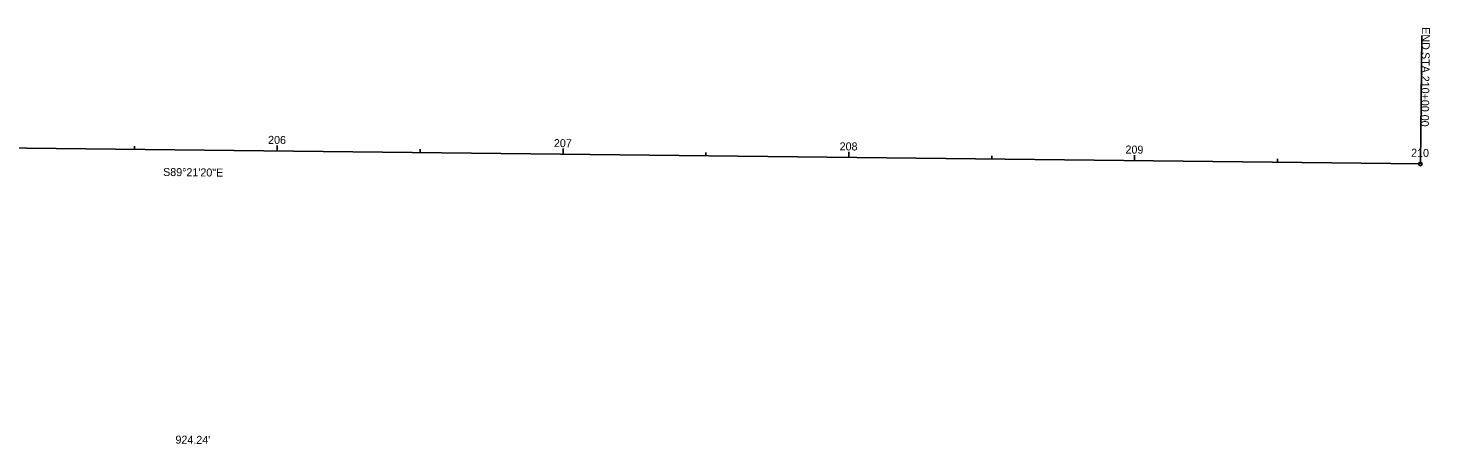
# Model space of a CAD drawing. Extents: x 1501024 to 1508874, y 327839 to 328839.
# Drawn here: x 1508383 to 1508873.6, y 328154.4 to 328299.9 of the extents above; entities that cross this region are included whole.
import ezdxf

# ---------------------------------------------------------------- set-up
doc = ezdxf.new("R2010")
doc.units = 0
for name, color, linetype in [('GE_X_Alignment', 7, 'Continuous'), ('GE_X_Alignment_100_Bearings', 7, 'Continuous'), ('GE_X_Alignment_100_Cardinal_Points', 7, 'Continuous'), ('GE_X_Alignment_100_Distances', 7, 'Continuous'), ('GE_X_Alignment_100_Stations', 7, 'Continuous'), ('GE_X_Alignment_500_Bearings', 7, 'Continuous'), ('GE_X_Alignment_500_Cardinal_Points', 7, 'Continuous'), ('GE_X_Alignment_500_Distances', 7, 'Continuous'), ('GE_X_Alignment_500_Stations', 7, 'Continuous')]:
    doc.layers.add(name, color=color, linetype=linetype)

msp = doc.modelspace()

# ---------------------------------------------------------------- linework, layer by layer
at = {"layer": 'GE_X_Alignment'}
msp.add_line((1507946.04, 328262.76), (1508870.22, 328252.36), dxfattribs=at)
at = {"layer": 'GE_X_Alignment_100_Cardinal_Points'}
msp.add_line((1508870.22, 328252.36), (1508870.72, 328297.36), dxfattribs=at)
msp.add_circle((1508870.22, 328252.36), 0.6, dxfattribs=at)
at = {"layer": 'GE_X_Alignment_100_Stations'}
for p, q in [((1508420.25, 328257.43), (1508420.26, 328258.63)), ((1508470.24, 328256.86), (1508470.26, 328258.86)), ((1508520.24, 328256.3), (1508520.25, 328257.5)), ((1508570.24, 328255.74), (1508570.26, 328257.74)), ((1508620.23, 328255.18), (1508620.25, 328256.38)), ((1508670.23, 328254.61), (1508670.25, 328256.61)), ((1508720.23, 328254.05), (1508720.24, 328255.25)), ((1508770.22, 328253.49), (1508770.25, 328255.49)), ((1508870.22, 328252.36), (1508870.24, 328254.36)), ((1508820.22, 328252.93), (1508820.23, 328254.13))]:
    msp.add_line(p, q, dxfattribs=at)
at = {"layer": 'GE_X_Alignment_500_Cardinal_Points'}
msp.add_line((1508870.22, 328252.36), (1508870.72, 328297.36), dxfattribs=at)
msp.add_circle((1508870.22, 328252.36), 0.6, dxfattribs=at)
at = {"layer": 'GE_X_Alignment_500_Stations'}
for p, q in [((1508470.24, 328256.86), (1508470.26, 328258.06)), ((1508570.24, 328255.74), (1508570.25, 328256.94)), ((1508670.23, 328254.61), (1508670.24, 328255.81)), ((1508770.22, 328253.49), (1508770.24, 328254.69)), ((1508870.22, 328252.36), (1508870.24, 328254.36))]:
    msp.add_line(p, q, dxfattribs=at)

# ---------------------------------------------------------------- texts
at = {"layer": 'GE_X_Alignment_100_Bearings'}
msp.add_text('S89°21\'20"E', height=2.8, rotation=359.3556, dxfattribs=at).set_placement((1508430.28, 328248.18))
at = {"layer": 'GE_X_Alignment_100_Cardinal_Points'}
for s, p in [('END', (1508870.79, 328300.22)), (' STA. ', (1508870.71, 328292.57)), ('210+00.00', (1508870.6, 328283.25))]:
    msp.add_text(s, height=2.8, rotation=269.3556, dxfattribs=at).set_placement(p)
at = {"layer": 'GE_X_Alignment_100_Distances'}
msp.add_text("924.24'", height=2.8, rotation=359.3556, dxfattribs=at).set_placement((1508434.6, 328154.55))
at = {"layer": 'GE_X_Alignment_100_Stations'}
for s, p in [('206', (1508467.02, 328259.4)), ('207', (1508567.02, 328258.27)), ('208', (1508667.01, 328257.15)), ('209', (1508767.03, 328256.03)), ('210', (1508866.98, 328254.9))]:
    msp.add_text(s, height=2.8, rotation=359.3556, dxfattribs=at).set_placement(p)
at = {"layer": 'GE_X_Alignment_500_Bearings'}
msp.add_text('S89°21\'20"E', height=2.8, rotation=359.3556, dxfattribs=at).set_placement((1508430.28, 328248.18))
at = {"layer": 'GE_X_Alignment_500_Cardinal_Points'}
for s, p in [('END', (1508870.79, 328300.22)), (' STA. ', (1508870.71, 328292.57)), ('210+00.00', (1508870.6, 328283.25))]:
    msp.add_text(s, height=2.8, rotation=269.3556, dxfattribs=at).set_placement(p)
at = {"layer": 'GE_X_Alignment_500_Distances'}
msp.add_text("924.24'", height=2.8, rotation=359.3556, dxfattribs=at).set_placement((1508434.6, 328154.55))
at = {"layer": 'GE_X_Alignment_500_Stations'}
msp.add_text('210', height=2.8, rotation=359.3556, dxfattribs=at).set_placement((1508866.98, 328254.9))

doc.saveas('drawing.dxf')
